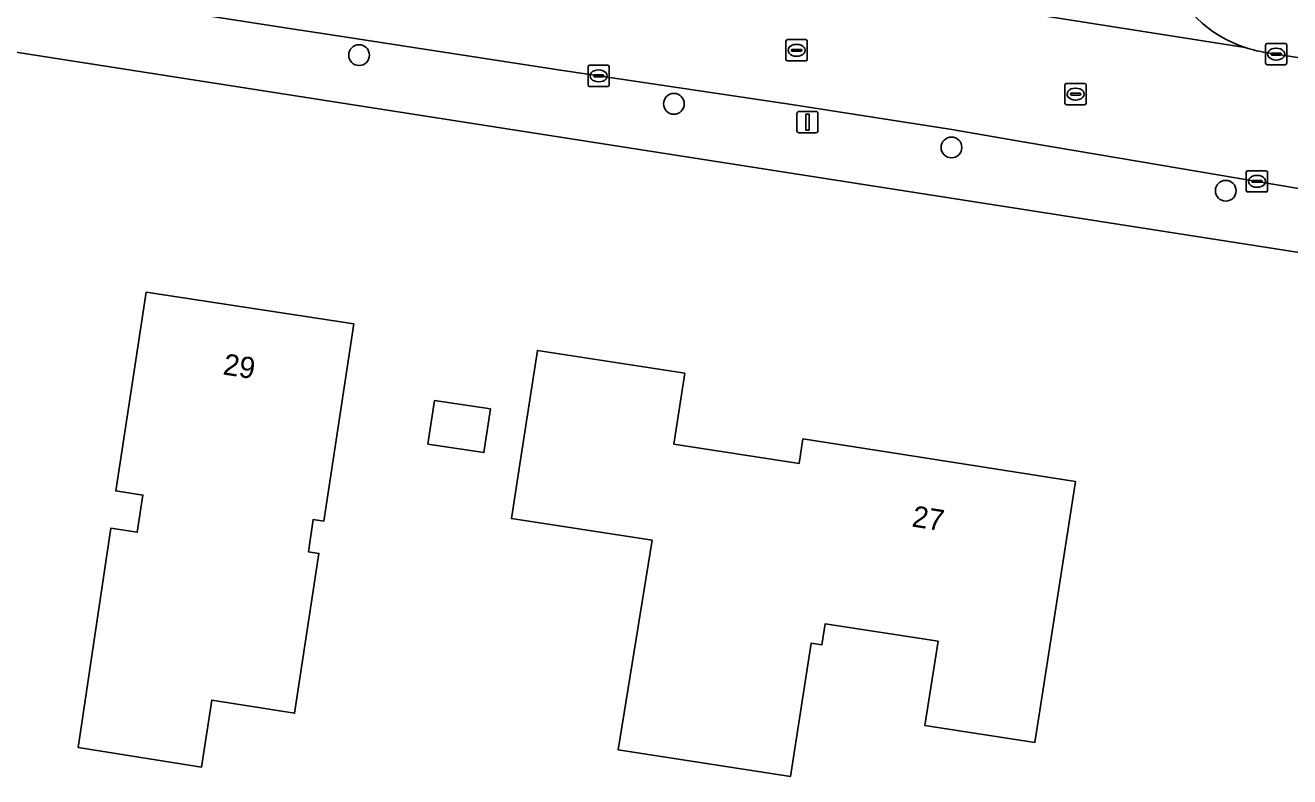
# Model space of a CAD drawing. Extents: x 161483 to 162250, y 379484 to 380833.
# Drawn here: x 161693.2 to 161752.7, y 380408.4 to 380443.7 of the extents above; entities that cross this region are included whole.
import ezdxf

# ---------------------------------------------------------------- set-up
doc = ezdxf.new("R2010")
doc.units = 0
for name, color, linetype in [('IMGEO_Boom', 7, 'Continuous'), ('IMGEO_Erf', 7, 'Continuous'), ('IMGEO_Kolk', 7, 'Continuous'), ('IMGEO_Lichtmast', 7, 'Continuous'), ('IMGEO_Pand', 7, 'Continuous'), ('IMGEO_Pand_nummerreeks', 7, 'Continuous'), ('IMGEO_Rijbaan_lokaal_open', 7, 'Continuous'), ('IMGEO_Rioolput', 7, 'Continuous'), ('IMGEO_Voetpad_open', 7, 'Continuous')]:
    doc.layers.add(name, color=color, linetype=linetype)

msp = doc.modelspace()

# ---------------------------------------------------------------- linework, layer by layer
at = {"layer": 'IMGEO_Boom'}
for centre in [(161708.906, 380442.314), (161723.725, 380440.023), (161736.79, 380437.973), (161749.7, 380435.936)]:
    msp.add_circle(centre, 0.489, dxfattribs=at)
at = {"layer": 'IMGEO_Erf'}
msp.add_lwpolyline([(162078.957, 380365.04), (162051.567, 380370.414), (162025.006, 380376.148), (162000, 380382.025), (161995.099, 380383.252), (161959.315, 380392.214), (161910.21, 380403.651), (161910.18, 380403.657), (161870.617, 380411.917), (161833.133, 380419.277), (161827.383, 380420.325), (161803.575, 380424.662), (161764.511, 380431.266), (161690.732, 380442.772), (161684.352, 380443.733), (161658.891, 380447.568)], dxfattribs=at)
for points in [[(161706.519, 380418.953), (161707.013, 380418.878), (161705.869, 380411.362), (161701.972, 380411.977), (161701.487, 380408.818), (161695.684, 380409.746), (161697.215, 380420.065), (161698.463, 380419.874), (161698.73, 380421.623), (161697.454, 380421.818), (161698.127, 380426.223), (161698.881, 380431.165), (161708.665, 380429.671), (161707.911, 380424.729), (161707.25, 380420.401), (161706.752, 380420.477)], [(161740.715, 380409.986), (161735.541, 380410.791), (161736.156, 380414.745), (161730.845, 380415.571), (161730.689, 380414.573), (161730.183, 380414.651), (161729.208, 380408.381), (161721.103, 380409.642), (161722.699, 380419.496), (161716.077, 380420.52), (161716.536, 380423.484), (161717.3, 380428.425), (161724.237, 380427.349), (161723.721, 380424.018), (161729.62, 380423.104), (161729.799, 380424.26), (161733.914, 380423.62), (161742.624, 380422.264), (161741.856, 380417.324)], [(161714.779, 380423.617), (161712.147, 380424.019), (161712.461, 380426.074), (161715.093, 380425.672)]]:
    msp.add_lwpolyline(points, close=True, dxfattribs=at)
at = {"layer": 'IMGEO_Kolk'}
for p, q in [((161751.647, 380442.862), (161752.499, 380442.862)), ((161751.572, 380441.936), (161751.572, 380442.788)), ((161751.831, 380442.356), (161751.831, 380442.368)), ((161752.269, 380442.319), (161751.871, 380442.319)), ((161751.874, 380442.405), (161752.272, 380442.405)), ((161752.06, 380442.642), (161752.085, 380442.642)), ((161752.315, 380442.368), (161752.315, 380442.356)), ((161752.573, 380442.788), (161752.573, 380441.936)), ((161719.683, 380440.913), (161719.683, 380441.765)), ((161719.758, 380441.839), (161720.61, 380441.839)), ((161720.684, 380441.765), (161720.684, 380440.913)), ((161752.499, 380441.862), (161751.647, 380441.862)), ((161752.083, 380442.082), (161752.058, 380442.082)), ((161719.942, 380441.333), (161719.942, 380441.345)), ((161720.38, 380441.296), (161719.982, 380441.296)), ((161719.985, 380441.382), (161720.383, 380441.382)), ((161720.171, 380441.619), (161720.196, 380441.619)), ((161720.426, 380441.345), (161720.426, 380441.333)), ((161720.61, 380440.839), (161719.758, 380440.839)), ((161720.194, 380441.059), (161720.169, 380441.059)), ((161750.667, 380435.951), (161750.667, 380436.803)), ((161750.742, 380436.877), (161751.594, 380436.877)), ((161750.926, 380436.371), (161750.926, 380436.383)), ((161751.364, 380436.334), (161750.966, 380436.334)), ((161750.969, 380436.42), (161751.367, 380436.42)), ((161751.155, 380436.657), (161751.18, 380436.657)), ((161751.41, 380436.383), (161751.41, 380436.371)), ((161751.668, 380436.803), (161751.668, 380435.951)), ((161751.594, 380435.877), (161750.742, 380435.877)), ((161751.178, 380436.097), (161751.153, 380436.097))]:
    msp.add_line(p, q, dxfattribs=at)
for points in [[(161751.647, 380442.862), (161752.499, 380442.862)], [(161751.572, 380441.936), (161751.572, 380442.788)], [(161752.573, 380442.788), (161752.573, 380441.936)], [(161719.683, 380440.913), (161719.683, 380441.765)], [(161719.758, 380441.839), (161720.61, 380441.839)], [(161720.684, 380441.765), (161720.684, 380440.913)], [(161752.499, 380441.862), (161751.647, 380441.862)], [(161720.61, 380440.839), (161719.758, 380440.839)], [(161750.667, 380435.951), (161750.667, 380436.803)], [(161750.742, 380436.877), (161751.594, 380436.877)], [(161751.668, 380436.803), (161751.668, 380435.951)], [(161751.594, 380435.877), (161750.742, 380435.877)]]:
    msp.add_lwpolyline(points, dxfattribs=at)
for centre, radius, start, end in [((161751.649, 380442.786), 0.0765, 91.55205, 178.44795), ((161751.649, 380442.786), 0.0765, 91.55205, 178.44795), ((161752.497, 380442.786), 0.0765, 1.55205, 88.44795), ((161752.497, 380442.786), 0.0765, 1.55205, 88.44795), ((161751.871, 380442.365), 0.0403, 85.87752, 175.75265), ((161751.868, 380442.355), 0.0366, 178.93798, 274.71019), ((161752.272, 380442.362), 0.043, 264.86636, 352.45326), ((161752.276, 380442.367), 0.0386, 1.73085, 96.63898), ((161719.76, 380441.763), 0.0765, 91.55205, 178.44795), ((161719.76, 380441.763), 0.0765, 91.55205, 178.44795), ((161720.608, 380441.763), 0.0765, 1.55205, 88.44795), ((161720.608, 380441.763), 0.0765, 1.55205, 88.44795), ((161751.649, 380441.938), 0.0765, 181.55205, 268.44795), ((161751.649, 380441.938), 0.0765, 181.55205, 268.44795), ((161752.497, 380441.938), 0.0765, 271.55205, 358.44795), ((161752.497, 380441.938), 0.0765, 271.55205, 358.44795), ((161719.982, 380441.342), 0.0403, 85.87752, 175.75265), ((161719.979, 380441.332), 0.0366, 178.93798, 274.71019), ((161720.383, 380441.339), 0.043, 264.86636, 352.45326), ((161720.387, 380441.344), 0.0386, 1.73085, 96.63898), ((161719.76, 380440.915), 0.0765, 181.55205, 268.44795), ((161719.76, 380440.915), 0.0765, 181.55205, 268.44795), ((161720.608, 380440.915), 0.0765, 271.55205, 358.44795), ((161720.608, 380440.915), 0.0765, 271.55205, 358.44795), ((161750.744, 380436.801), 0.0765, 91.55205, 178.44795), ((161750.744, 380436.801), 0.0765, 91.55205, 178.44795), ((161750.966, 380436.38), 0.0403, 85.87752, 175.75265), ((161750.963, 380436.37), 0.0366, 178.93798, 274.71019), ((161751.367, 380436.377), 0.043, 264.86636, 352.45326), ((161751.371, 380436.382), 0.0386, 1.73085, 96.63898), ((161751.592, 380436.801), 0.0765, 1.55205, 88.44795), ((161751.592, 380436.801), 0.0765, 1.55205, 88.44795), ((161750.744, 380435.953), 0.0765, 181.55205, 268.44795), ((161750.744, 380435.953), 0.0765, 181.55205, 268.44795), ((161751.592, 380435.953), 0.0765, 271.55205, 358.44795), ((161751.592, 380435.953), 0.0765, 271.55205, 358.44795)]:
    msp.add_arc(centre, radius, start, end, dxfattribs=at)
for centre, major_axis, ratio, start_param, end_param in [((161752.059, 380442.362), (-0.387, 0.002), 0.722429, 4.712389, 7.853982), ((161752.084, 380442.362), (-0.39, 0.002), 0.717154, 1.570796, 4.712389), ((161720.17, 380441.339), (-0.387, 0.002), 0.722429, 4.712389, 7.853982), ((161720.195, 380441.339), (-0.39, 0.002), 0.717154, 1.570796, 4.712389), ((161751.154, 380436.377), (-0.387, 0.002), 0.722429, 4.712389, 7.853982), ((161751.179, 380436.377), (-0.39, 0.002), 0.717154, 1.570796, 4.712389)]:
    msp.add_ellipse(centre, major_axis=major_axis, ratio=ratio, start_param=start_param, end_param=end_param, dxfattribs=at)
at = {"layer": 'IMGEO_Lichtmast'}
for p, q in [((161729.516, 380438.767), (161729.516, 380439.567)), ((161729.516, 380439.567), (161729.516, 380438.767)), ((161729.616, 380439.667), (161730.406, 380439.667)), ((161730.406, 380439.667), (161729.616, 380439.667)), ((161730.506, 380439.567), (161730.506, 380438.767)), ((161730.506, 380438.767), (161730.506, 380439.567)), ((161730.406, 380438.667), (161729.616, 380438.667)), ((161729.616, 380438.667), (161730.406, 380438.667))]:
    msp.add_line(p, q, dxfattribs=at)
msp.add_lwpolyline([(161729.936, 380439.542), (161730.086, 380439.542), (161730.086, 380438.792), (161729.936, 380438.792), (161729.936, 380439.542)], dxfattribs=at)
for centre, start, end in [((161729.616, 380439.567), 90, 180), ((161729.616, 380439.567), 90, 180), ((161730.406, 380439.567), 0, 90), ((161730.406, 380439.567), 360, 90), ((161729.616, 380438.767), 180, 270), ((161729.616, 380438.767), 180, 270), ((161730.406, 380438.767), 270, 0), ((161730.406, 380438.767), 270, 0)]:
    msp.add_arc(centre, 0.1, start, end, dxfattribs=at)
at = {"layer": 'IMGEO_Pand'}
for points in [[(161706.752, 380420.477), (161707.25, 380420.401), (161707.911, 380424.729), (161708.665, 380429.671), (161698.881, 380431.165), (161698.127, 380426.223), (161697.454, 380421.818), (161698.73, 380421.623), (161698.463, 380419.874), (161697.215, 380420.065), (161695.684, 380409.746), (161701.487, 380408.818), (161701.972, 380411.977), (161705.869, 380411.362), (161707.013, 380418.878), (161706.519, 380418.953)], [(161742.624, 380422.264), (161733.914, 380423.62), (161729.799, 380424.26), (161729.62, 380423.104), (161723.721, 380424.018), (161724.237, 380427.349), (161717.3, 380428.425), (161716.536, 380423.484), (161716.077, 380420.52), (161722.699, 380419.496), (161721.103, 380409.642), (161729.208, 380408.381), (161730.183, 380414.651), (161730.689, 380414.573), (161730.845, 380415.571), (161736.156, 380414.745), (161735.541, 380410.791), (161740.715, 380409.986), (161741.856, 380417.324)], [(161712.147, 380424.019), (161714.779, 380423.617), (161715.093, 380425.672), (161712.461, 380426.074)]]:
    msp.add_lwpolyline(points, close=True, dxfattribs=at)
at = {"layer": 'IMGEO_Rijbaan_lokaal_open'}
for points in [[(161750.621, 380442.671), (161722.958, 380447.035)], [(161722.958, 380447.035), (161750.621, 380442.671)], [(161691.17, 380445.817), (161699.969, 380444.448), (161705.835, 380443.535), (161707.293, 380443.311), (161718.187, 380441.637), (161725.346, 380440.572), (161729.261, 380439.989), (161729.763, 380439.91), (161736.799, 380438.809), (161740.249, 380438.226), (161744.785, 380437.458), (161754.881, 380435.751)], [(161764.573, 380440.4), (161751.68, 380442.423)]]:
    msp.add_lwpolyline(points, dxfattribs=at)
for centre, radius, start, end in [((161752.521, 380448.405), 6.041, 200.66877, 251.66824), ((161752.517, 380448.383), 6.018, 251.63518, 262.00443)]:
    msp.add_arc(centre, radius, start, end, dxfattribs=at)
at = {"layer": 'IMGEO_Rioolput'}
for p, q in [((161729, 380442.116), (161729, 380442.968)), ((161729.075, 380443.042), (161729.927, 380443.042)), ((161730.001, 380442.968), (161730.001, 380442.116)), ((161729.259, 380442.536), (161729.259, 380442.548)), ((161729.697, 380442.499), (161729.299, 380442.499)), ((161729.302, 380442.585), (161729.7, 380442.585)), ((161729.511, 380442.262), (161729.486, 380442.262)), ((161729.488, 380442.822), (161729.513, 380442.822)), ((161729.743, 380442.548), (161729.743, 380442.536)), ((161729.927, 380442.042), (161729.075, 380442.042)), ((161742.13, 380440.055), (161742.13, 380440.907)), ((161742.205, 380440.981), (161743.057, 380440.981)), ((161742.389, 380440.475), (161742.389, 380440.487)), ((161742.432, 380440.524), (161742.83, 380440.524)), ((161742.618, 380440.761), (161742.643, 380440.761)), ((161742.873, 380440.487), (161742.873, 380440.475)), ((161743.131, 380440.907), (161743.131, 380440.055)), ((161743.057, 380439.981), (161742.205, 380439.981)), ((161742.827, 380440.438), (161742.429, 380440.438)), ((161742.641, 380440.201), (161742.616, 380440.201))]:
    msp.add_line(p, q, dxfattribs=at)
for points in [[(161729, 380442.116), (161729, 380442.968)], [(161729.075, 380443.042), (161729.927, 380443.042)], [(161730.001, 380442.968), (161730.001, 380442.116)], [(161729.927, 380442.042), (161729.075, 380442.042)], [(161742.13, 380440.055), (161742.13, 380440.907)], [(161742.205, 380440.981), (161743.057, 380440.981)], [(161743.131, 380440.907), (161743.131, 380440.055)], [(161743.057, 380439.981), (161742.205, 380439.981)]]:
    msp.add_lwpolyline(points, dxfattribs=at)
for centre, radius, start, end in [((161729.077, 380442.966), 0.0765, 91.55205, 178.44795), ((161729.077, 380442.966), 0.0765, 91.55205, 178.44795), ((161729.925, 380442.966), 0.0765, 1.55205, 88.44795), ((161729.925, 380442.966), 0.0765, 1.55205, 88.44795), ((161729.299, 380442.545), 0.0403, 85.87752, 175.75265), ((161729.296, 380442.535), 0.0366, 178.93798, 274.71019), ((161729.7, 380442.542), 0.043, 264.86636, 352.45326), ((161729.704, 380442.547), 0.0386, 1.73085, 96.63898), ((161729.077, 380442.118), 0.0765, 181.55205, 268.44795), ((161729.077, 380442.118), 0.0765, 181.55205, 268.44795), ((161729.925, 380442.118), 0.0765, 271.55205, 358.44795), ((161729.925, 380442.118), 0.0765, 271.55205, 358.44795), ((161742.207, 380440.905), 0.0765, 91.55205, 178.44795), ((161742.207, 380440.905), 0.0765, 91.55205, 178.44795), ((161742.429, 380440.484), 0.0403, 85.87752, 175.75265), ((161742.426, 380440.474), 0.0366, 178.93798, 274.71019), ((161742.83, 380440.481), 0.043, 264.86636, 352.45326), ((161742.834, 380440.486), 0.0386, 1.73085, 96.63898), ((161743.055, 380440.905), 0.0765, 1.55205, 88.44795), ((161743.055, 380440.905), 0.0765, 1.55205, 88.44795), ((161742.207, 380440.057), 0.0765, 181.55205, 268.44795), ((161742.207, 380440.057), 0.0765, 181.55205, 268.44795), ((161743.055, 380440.057), 0.0765, 271.55205, 358.44795), ((161743.055, 380440.057), 0.0765, 271.55205, 358.44795)]:
    msp.add_arc(centre, radius, start, end, dxfattribs=at)
for centre, major_axis, ratio, start_param, end_param in [((161729.487, 380442.542), (-0.387, 0.002), 0.722429, 4.712389, 7.853982), ((161729.512, 380442.542), (-0.39, 0.002), 0.717154, 1.570796, 4.712389), ((161742.617, 380440.481), (-0.387, 0.002), 0.722429, 4.712389, 7.853982), ((161742.642, 380440.481), (-0.39, 0.002), 0.717154, 1.570796, 4.712389)]:
    msp.add_ellipse(centre, major_axis=major_axis, ratio=ratio, start_param=start_param, end_param=end_param, dxfattribs=at)
at = {"layer": 'IMGEO_Voetpad_open'}
for points in [[(161754.881, 380435.751), (161744.785, 380437.458), (161740.249, 380438.226), (161736.799, 380438.809), (161729.763, 380439.91), (161729.261, 380439.989), (161725.346, 380440.572), (161718.187, 380441.637), (161707.293, 380443.311), (161705.835, 380443.535), (161699.969, 380444.448), (161691.17, 380445.817), (161690.732, 380442.772), (161764.511, 380431.266)], [(161751.68, 380442.423), (161764.573, 380440.4), (161768.452, 380439.791), (161769.059, 380439.687), (161771.448, 380439.277), (161775.879, 380438.531), (161785.575, 380436.899), (161787.48, 380436.57), (161795.804, 380435.133), (161800.051, 380434.4), (161811.738, 380432.305), (161812.021, 380432.261), (161812.858, 380432.129)]]:
    msp.add_lwpolyline(points, dxfattribs=at)
for centre, radius, start, end in [((161752.521, 380448.405), 6.041, 200.66877, 251.66824), ((161752.517, 380448.383), 6.018, 251.63518, 262.00443)]:
    msp.add_arc(centre, radius, start, end, dxfattribs=at)

# ---------------------------------------------------------------- texts
at = {"layer": 'IMGEO_Pand_nummerreeks'}
for s, rotation, p in [('29', 351.31969, (161702.461, 380427.3)), ('27', 351.15382, (161734.891, 380420.148))]:
    msp.add_text(s, height=1, rotation=rotation, dxfattribs=at).set_placement(p)

doc.saveas('drawing.dxf')
